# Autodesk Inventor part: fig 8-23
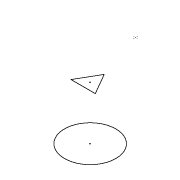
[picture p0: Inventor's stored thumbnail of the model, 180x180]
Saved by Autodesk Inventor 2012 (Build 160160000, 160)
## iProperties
Shininess: 77.0
Angle Display Precision: 2
Document Length Units: 11269
Document Angle Units: 11279
Document Time Units: 11290
Document Mass Units: 11283
Document Length Units Precision: 3
Document Angle Units Precision: 2
Created: 2001-12
Part Number: fig 8-23
Document SubType Name: Modeling
Designer: CADSoft
Density: 1 g/cm^3
Material: Default
Density: 0.0
Volumn: 0.0
Area: 0.0
PropertySet Name: Model Information
Control State: 0
Master: False
Checked Out: False
Author: CADSoft
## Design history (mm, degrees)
workplane "Work Plane3"
workplane "Work Plane4"
sketch "Sketch12"
  geometry: L1 (0, 10.598)-(9.178, -5.299); L2 (9.178, -5.299)-(-9.178, -5.299); L3 (-9.178, -5.299)-(0, 10.598); 1 further point
  constraints: 6 end point, 5 other
workplane "Work Plane5"
sketch "Sketch1"
  geometry: C1 r 19.387 at (0, 0); 1 further point
  constraints: 1 centre point, 1 coincident, 1 other
sketch "Sketch2"
  geometry: 1 further point
